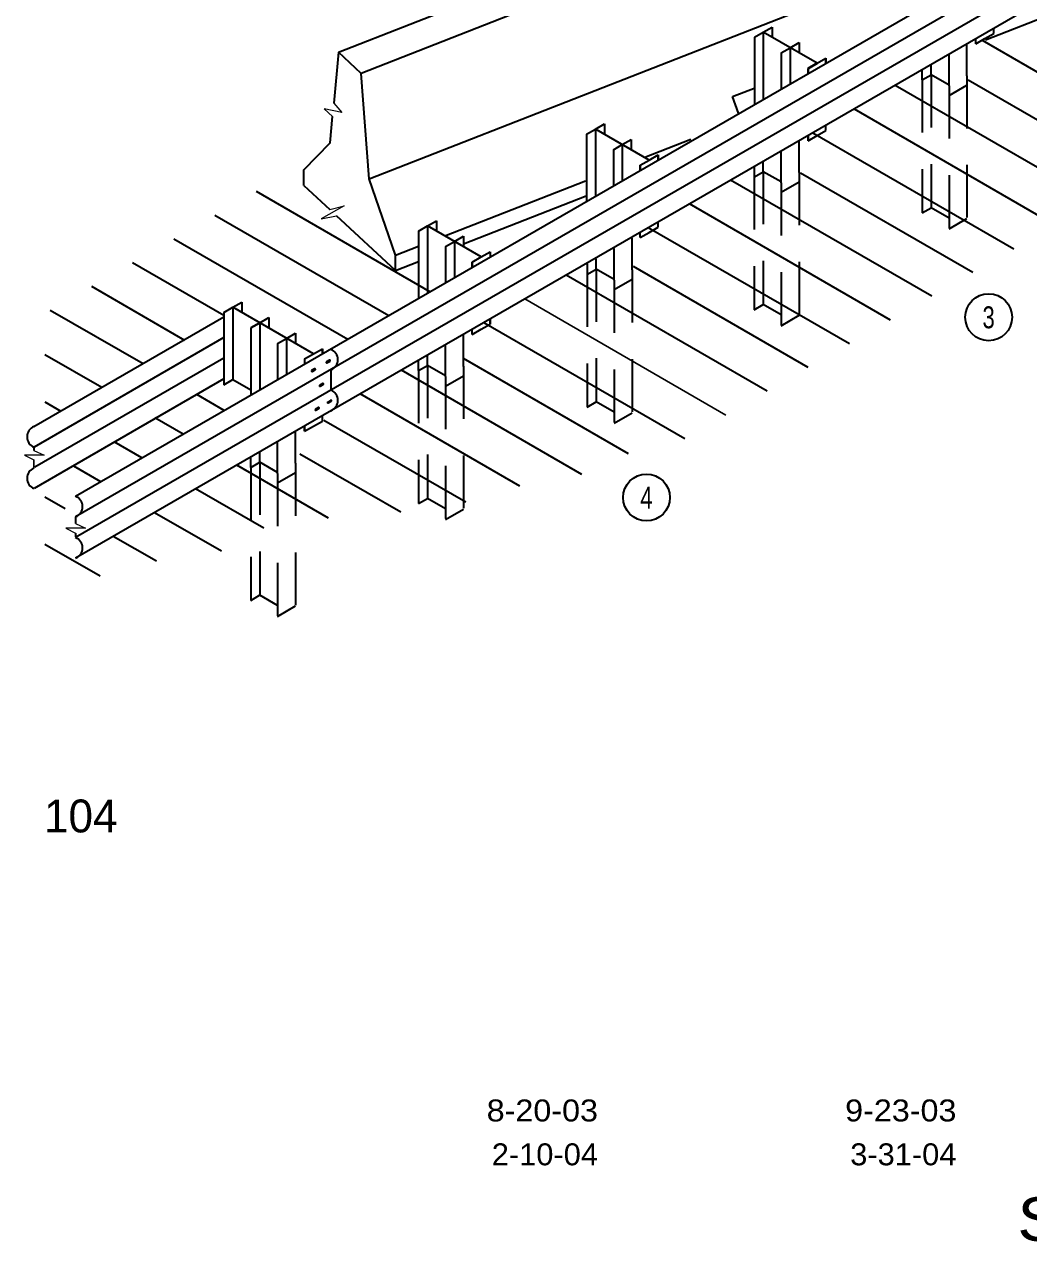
# Model space of a CAD drawing. Extents: x 12.4 to 19.52, y 6.05 to 15.92.
# Drawn here: x 12.509 to 15.254, y 6.05 to 9.379 of the extents above; entities that cross this region are included whole.
import ezdxf
from ezdxf.enums import TextEntityAlignment as Align

# ---------------------------------------------------------------- set-up
doc = ezdxf.new("R2010")
doc.units = 0
doc.header["$LTSCALE"] = 0.024
doc.linetypes.add('LONG_DASHED', pattern=[7.5, 6, -1.5])
for name, color, linetype, lineweight in [('1', 7, 'Continuous', 35), ('10', 7, 'Continuous', 13), ('12', 7, 'Continuous', 53)]:
    doc.layers.add(name, color=color, linetype=linetype, lineweight=lineweight)
doc.layers.add('13', color=7, linetype='Continuous')

msp = doc.modelspace()

# ---------------------------------------------------------------- linework, layer by layer
at = {"layer": '1'}
for p, q in [((19.1506, 11.786), (12.649, 8.0324)), ((19.1513, 11.7299), (12.649, 7.9758)), ((19.1513, 11.6733), (12.649, 7.9193)), ((12.649, 8.0888), (17.757, 11.038)), ((13.3674, 9.3032), (15.248, 10.0395)), ((15.31, 9.9818), (13.4295, 9.2454)), ((13.4515, 8.9566), (14.9635, 9.5486)), ((15.1367, 9.3374), (15.4043, 9.4423)), ((14.5046, 9.3439), (14.5291, 9.358)), ((14.5291, 9.358), (14.5536, 9.3721)), ((14.5536, 9.3721), (14.5536, 9.3449)), ((15.1593, 9.3545), (15.1593, 9.3686)), ((14.5046, 9.3439), (14.5046, 9.1601)), ((14.6025, 9.3156), (14.6269, 9.3297)), ((14.6269, 9.3297), (14.6269, 9.3014)), ((15.0859, 9.2388), (15.0859, 9.3262)), ((15.1103, 9.3262), (15.1103, 9.3403)), ((15.127, 9.3358), (15.6645, 9.0254)), ((13.3674, 9.3032), (13.3546, 9.1634)), ((14.578, 9.3014), (14.6025, 9.3156)), ((14.578, 9.3014), (14.578, 9.2025)), ((14.6025, 9.3156), (14.6025, 9.2166)), ((14.6269, 9.3014), (14.6269, 9.3003)), ((15.0369, 9.2108), (15.0369, 9.298)), ((14.6759, 9.2732), (14.7004, 9.2873)), ((14.9635, 9.2272), (14.9635, 9.2554)), ((14.9636, 9.2272), (14.988, 9.2414)), ((15.0893, 9.2276), (15.552, 8.9605)), ((14.4453, 9.182), (14.5065, 9.206)), ((14.8897, 9.2129), (15.4395, 8.8955)), ((15.0369, 9.185), (15.0859, 9.2134)), ((14.461, 9.1366), (14.4453, 9.182)), ((14.7772, 9.1479), (15.3269, 8.8305)), ((14.0457, 9.0789), (14.0701, 9.093)), ((14.0701, 9.093), (14.0947, 9.1071)), ((14.0701, 9.093), (14.0701, 8.9093)), ((14.2171, 9.0083), (14.0726, 9.0917)), ((14.0947, 9.1071), (14.0947, 9.0799)), ((14.7004, 9.0895), (14.7004, 9.1036)), ((14.0457, 9.0789), (14.0457, 8.8952)), ((14.1436, 9.0506), (14.1681, 9.0647)), ((14.1681, 9.0647), (14.1681, 9.0365)), ((14.3312, 9.0644), (14.2052, 9.0151)), ((14.627, 8.9739), (14.627, 9.0613)), ((14.6647, 9.083), (15.2144, 8.7656)), ((14.1191, 9.0365), (14.1436, 9.0506)), ((14.1191, 9.0365), (14.1191, 8.9376)), ((14.1436, 9.0506), (14.1436, 8.9517)), ((14.2171, 9.0083), (14.2415, 9.0224)), ((14.578, 8.9459), (14.578, 9.0331)), ((14.1925, 8.9942), (14.2171, 9.0083)), ((14.5046, 8.9623), (14.5046, 8.9905)), ((14.5047, 8.9623), (14.5291, 8.9765)), ((15.1019, 8.7006), (14.6308, 8.9726)), ((13.1424, 8.9228), (13.618, 8.6483)), ((13.2727, 8.939), (13.3438, 8.873)), ((13.6582, 8.801), (14.0433, 8.9517)), ((14.9894, 8.6357), (14.4397, 8.9531)), ((14.578, 8.9201), (14.627, 8.9485)), ((14.0447, 8.9099), (13.7092, 8.7785)), ((13.0299, 8.8579), (13.5055, 8.5833)), ((13.5236, 8.7059), (13.3623, 8.8557)), ((14.8769, 8.5707), (14.3272, 8.8882)), ((13.5868, 8.814), (13.6113, 8.8281)), ((13.6113, 8.8281), (13.6357, 8.8422)), ((13.6357, 8.8422), (13.6357, 8.8149)), ((14.7645, 8.5058), (14.2147, 8.8232)), ((14.2415, 8.8245), (14.2415, 8.8386)), ((12.9175, 8.7929), (13.393, 8.5184)), ((13.5868, 8.814), (13.5868, 8.6303)), ((13.6846, 8.7857), (13.7092, 8.7998)), ((13.7092, 8.7998), (13.7092, 8.7716)), ((14.1705, 8.7076), (14.1705, 8.795)), ((14.1925, 8.7963), (14.1925, 8.8104)), ((13.5236, 8.7482), (13.5868, 8.773)), ((13.6603, 8.7716), (13.6846, 8.7857)), ((13.6603, 8.7716), (13.6603, 8.6726)), ((13.6846, 8.7857), (13.6846, 8.6867)), ((13.7581, 8.7433), (13.7826, 8.7574)), ((13.7826, 8.7574), (13.7826, 8.7433)), ((14.1215, 8.6796), (14.1215, 8.7668)), ((12.805, 8.728), (13.0545, 8.5839)), ((13.5236, 8.7059), (13.5868, 8.7306)), ((13.7336, 8.7292), (13.7581, 8.7433)), ((14.0481, 8.696), (14.0481, 8.7242)), ((14.5395, 8.3759), (13.9897, 8.6933)), ((14.0482, 8.696), (14.0726, 8.7102)), ((14.652, 8.4408), (14.1738, 8.717)), ((12.6925, 8.663), (12.947, 8.516)), ((14.1215, 8.6538), (14.1705, 8.6822)), ((12.5799, 8.5981), (12.8335, 8.4517)), ((13.0545, 8.5913), (13.079, 8.6055)), ((13.0545, 8.5913), (13.0545, 8.3936)), ((13.079, 8.6055), (13.1034, 8.6197)), ((13.2992, 8.4783), (13.079, 8.6055)), ((13.079, 8.6055), (13.079, 8.4077)), ((13.1034, 8.6197), (13.1034, 8.5905)), ((12.5353, 8.2795), (13.0545, 8.5793)), ((13.1524, 8.5631), (13.1769, 8.5773)), ((13.1524, 8.5631), (13.1524, 8.3795)), ((13.1769, 8.5773), (13.1769, 8.55)), ((14.3145, 8.246), (13.7647, 8.5634)), ((13.0545, 8.5228), (12.5358, 8.2232)), ((13.1279, 8.549), (13.1279, 8.3653)), ((13.2258, 8.5207), (13.2503, 8.5349)), ((13.2503, 8.5349), (13.2503, 8.5066)), ((13.7092, 8.444), (13.7092, 8.5314)), ((13.7336, 8.5313), (13.7336, 8.5454)), ((13.2013, 8.5066), (13.2258, 8.5207)), ((13.2013, 8.5066), (13.2013, 8.4077)), ((13.2258, 8.5207), (13.2258, 8.4218)), ((13.2992, 8.4783), (13.3237, 8.4924)), ((13.6602, 8.416), (13.6602, 8.5032)), ((13.0545, 8.4662), (12.5378, 8.1681)), ((12.5648, 8.4769), (12.721, 8.3867)), ((13.2748, 8.4642), (13.2992, 8.4783)), ((13.2748, 8.4642), (13.2748, 8.4501)), ((13.3432, 8.4611), (13.3348, 8.4563)), ((13.3363, 8.4539), (13.3447, 8.4587)), ((13.5868, 8.4324), (13.5868, 8.4606)), ((14.1605, 8.205), (13.7092, 8.4656)), ((13.3026, 8.4375), (13.2942, 8.4326)), ((13.2956, 8.4302), (13.304, 8.435)), ((13.3472, 8.4341), (13.3472, 8.3794)), ((14.0332, 8.1485), (13.5397, 8.4335)), ((13.5869, 8.4324), (13.6113, 8.4466)), ((13.0545, 8.4097), (12.5356, 8.1103)), ((13.0542, 8.4055), (13.0542, 8.4067)), ((13.0545, 8.3936), (13.079, 8.4077)), ((13.079, 8.4077), (13.1279, 8.3795)), ((13.3246, 8.397), (13.3162, 8.3921)), ((13.3177, 8.3897), (13.326, 8.3945)), ((13.6602, 8.3902), (13.7092, 8.4186)), ((13.0555, 8.3235), (12.9801, 8.3671)), ((13.8637, 8.1165), (13.4272, 8.3685)), ((12.5648, 8.347), (12.6085, 8.3218)), ((13.3127, 8.3312), (13.3044, 8.3263)), ((13.3058, 8.3239), (13.3141, 8.3287)), ((13.3466, 8.3514), (13.3383, 8.3465)), ((13.3397, 8.3441), (13.348, 8.3489)), ((12.943, 8.2585), (12.8659, 8.303)), ((13.3237, 8.2946), (13.3237, 8.3087)), ((13.7155, 8.0722), (13.3273, 8.2963)), ((13.2503, 8.179), (13.2503, 8.2664)), ((12.5353, 8.2229), (12.5353, 8.214)), ((12.8305, 8.1936), (12.7549, 8.2372)), ((13.2013, 8.151), (13.2013, 8.2382)), ((13.1279, 8.1674), (13.1279, 8.1956)), ((13.5378, 8.0449), (13.2622, 8.204)), ((12.718, 8.1287), (12.6442, 8.1713)), ((13.3405, 8.029), (13.0897, 8.1737)), ((13.128, 8.1674), (13.1524, 8.1816)), ((13.2013, 8.1252), (13.2503, 8.1536)), ((13.1635, 8.0012), (12.9772, 8.1088)), ((12.5648, 8.0871), (12.6202, 8.0552)), ((12.649, 8.0324), (12.649, 8.0142)), ((13.0477, 7.9382), (12.8647, 8.0438)), ((12.7159, 7.8699), (12.5648, 7.9571)), ((12.649, 7.9883), (12.649, 7.9776)), ((12.8701, 7.9109), (12.7522, 7.9789))]:
    msp.add_line(p, q, dxfattribs=at)
at = {"layer": '1', "lineweight": 40}
for p, q in [((14.6515, 9.2591), (14.6759, 9.2732)), ((14.6515, 9.2591), (14.6515, 9.2449)), ((14.7004, 9.2873), (14.7004, 9.2732)), ((14.6515, 9.2449), (14.6515, 9.2444)), ((14.6515, 9.0611), (14.6515, 9.0754)), ((14.2415, 9.0224), (14.2415, 9.0083)), ((14.1925, 8.9942), (14.1925, 8.98)), ((13.7092, 8.7716), (13.7092, 8.7704)), ((13.7336, 8.7292), (13.7336, 8.7151)), ((13.7336, 8.7151), (13.7336, 8.7145)), ((13.1279, 8.549), (13.1524, 8.5631)), ((13.7826, 8.5595), (13.7826, 8.5737)), ((13.3237, 8.4924), (13.3237, 8.4783)), ((13.2748, 8.2664), (13.2748, 8.2805))]:
    msp.add_line(p, q, dxfattribs=at)
at = {"layer": '1', "linetype": 'LONG_DASHED'}
for p, q in [((14.988, 9.2414), (14.988, 8.8778)), ((15.0859, 9.239), (15.0859, 8.8486)), ((14.5291, 8.9765), (14.5291, 8.6129)), ((14.627, 8.9741), (14.627, 8.5837)), ((15.0369, 8.8496), (14.988, 8.8778)), ((14.0726, 8.7102), (14.0726, 8.3466)), ((14.1705, 8.7078), (14.1705, 8.3174)), ((14.578, 8.5847), (14.5291, 8.6129)), ((13.6113, 8.4466), (13.6113, 8.083)), ((13.7092, 8.4442), (13.7092, 8.0538)), ((14.1215, 8.3184), (14.0726, 8.3466)), ((13.1524, 8.1816), (13.1524, 7.818)), ((13.2503, 8.1792), (13.2503, 7.7888)), ((13.6602, 8.0548), (13.6113, 8.083)), ((13.2013, 7.7898), (13.1524, 7.818))]:
    msp.add_line(p, q, dxfattribs=at)
at = {"layer": '1', "lineweight": 25}
for p, q in [((14.427, 8.3109), (13.8772, 8.6284)), ((12.5353, 8.1881), (12.5353, 8.1662))]:
    msp.add_line(p, q, dxfattribs=at)
at = {"layer": '1'}
for points in [[(14.6515, 9.2591), (14.6759, 9.2732), (14.5291, 9.358), (14.5291, 9.1743)], [(15.1103, 9.3262), (15.1348, 9.3403), (15.1593, 9.3545)], [(13.5236, 8.7059), (13.5236, 8.7482), (13.4515, 8.9566), (13.4295, 9.2454), (13.3674, 9.3032)], [(15.0369, 9.2132), (14.988, 9.2414), (14.988, 9.2696)], [(13.2727, 8.939), (13.2727, 8.9813), (13.3448, 9.0557), (13.3514, 9.1277)], [(14.6515, 9.0611), (14.6759, 9.0754), (14.7004, 9.0895)], [(14.578, 8.9483), (14.5291, 8.9765), (14.5291, 9.0047)], [(13.7336, 8.7292), (13.7581, 8.7433), (13.6113, 8.8281), (13.6113, 8.6444)], [(14.1925, 8.7963), (14.2171, 8.8104), (14.2415, 8.8245)], [(14.1215, 8.682), (14.0726, 8.7102), (14.0726, 8.7384)], [(13.7336, 8.5313), (13.7581, 8.5454), (13.7826, 8.5595)], [(13.6602, 8.4184), (13.6113, 8.4466), (13.6113, 8.4748)], [(13.2748, 8.2664), (13.2992, 8.2805), (13.3237, 8.2946)], [(13.2013, 8.1534), (13.1524, 8.1816), (13.1524, 8.2098)]]:
    msp.add_lwpolyline(points, dxfattribs=at)
at = {"layer": '1', "linetype": 'LONG_DASHED'}
for points in [[(14.9634, 9.2272), (14.9634, 8.8638), (14.9878, 8.8778)], [(15.0369, 9.2108), (15.0369, 8.8202), (15.0859, 8.8486)], [(14.5045, 8.9623), (14.5045, 8.5989), (14.5289, 8.6129)], [(14.578, 8.9459), (14.578, 8.5553), (14.627, 8.5837)], [(14.048, 8.696), (14.048, 8.3326), (14.0724, 8.3466)], [(14.1215, 8.6796), (14.1215, 8.289), (14.1705, 8.3174)], [(13.5867, 8.4324), (13.5867, 8.069), (13.6111, 8.083)], [(13.6602, 8.416), (13.6602, 8.0254), (13.7092, 8.0538)], [(13.1278, 8.1674), (13.1278, 7.804), (13.1522, 7.818)], [(13.2013, 8.151), (13.2013, 7.7604), (13.2503, 7.7888)]]:
    msp.add_lwpolyline(points, dxfattribs=at)
at = {"layer": '1'}
for centre, radius, start, end in [((13.33546, 8.4624), 0.0306, 292.56091, 67.43909), ((13.33572, 8.4552), 0.00143, 126.00901, 293.99099), ((13.3438, 8.45987), 0.00143, 306.009, 113.99099), ((13.29507, 8.43154), 0.00143, 126.00901, 293.99099), ((13.30315, 8.43621), 0.00143, 306.009, 113.99099), ((13.31708, 8.39104), 0.00143, 126.00901, 293.99099), ((13.32517, 8.39571), 0.00143, 306.009, 113.99099), ((13.33546, 8.35112), 0.0306, 292.56091, 67.43909), ((13.30523, 8.32519), 0.00143, 126.00901, 293.99099), ((13.31332, 8.32986), 0.00143, 306.009, 113.99099), ((13.33913, 8.34544), 0.00143, 126.00901, 293.99099), ((13.34722, 8.35011), 0.00143, 306.009, 113.99099), ((12.54703, 8.25125), 0.0306, 112.56091, 247.43909), ((12.54703, 8.13792), 0.0306, 112.56091, 247.43909), ((12.63733, 8.06058), 0.0306, 292.56091, 67.43909), ((12.63733, 7.94754), 0.0306, 292.56091, 67.43909)]:
    msp.add_arc(centre, radius, start, end, dxfattribs=at)
at = {"layer": '10'}
for points in [[(13.3546, 9.1634), (13.3765, 9.1382), (13.329, 9.1483), (13.3514, 9.1277)], [(13.3438, 8.873), (13.3832, 8.8832), (13.3205, 8.8478), (13.3623, 8.8557)], [(12.5353, 8.214), (12.5629, 8.2015), (12.509, 8.201), (12.5353, 8.1881)], [(12.649, 8.0142), (12.6766, 8.0017), (12.6228, 8.0012), (12.649, 7.9883)]]:
    msp.add_lwpolyline(points, dxfattribs=at)
at = {"layer": '10', "lineweight": 35}
for centre in [(15.14514, 8.57837), (14.20974, 8.08539)]:
    msp.add_circle(centre, 0.06414, dxfattribs=at)

# ---------------------------------------------------------------- texts
at = {"layer": '1'}
for s, width, p in [('8-20-03', 1.1, (14.0771, 6.3791)), ('9-23-03', 1.1, (15.057, 6.3791)), ('2-10-04', 1.05, (14.0771, 6.2591)), ('3-31-04', 1.05, (15.057, 6.2591))]:
    msp.add_text(s, height=0.06, dxfattribs=dict(at, width=width)).set_placement(p, align=Align.RIGHT)
at = {"layer": '12', "width": 0.75}
for s, p in [('3', (15.145, 8.5482)), ('4', (14.2096, 8.0553))]:
    msp.add_text(s, height=0.06, dxfattribs=at).set_placement(p, align=Align.CENTER)
at = {"layer": '13'}
msp.add_text('104', height=0.09, dxfattribs=at).set_placement((12.6632, 7.1695), align=Align.CENTER)
at = {"layer": '13', "width": 1.15}
msp.add_text('STANDARD NO.', height=0.12, dxfattribs=at).set_placement((15.92075, 6.052), align=Align.CENTER)

doc.saveas('drawing.dxf')
